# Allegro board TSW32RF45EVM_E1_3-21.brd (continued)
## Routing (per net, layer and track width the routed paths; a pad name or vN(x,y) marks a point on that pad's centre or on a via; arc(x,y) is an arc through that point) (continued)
P3.3VLMX:
  vias: v1(109.22,18.16) v1(109.22,17.14) v1(109.22,16.13) v1(110.11,18.16) v1(110.11,17.14) v1(110.11,16.13) v1(111,18.16) v1(111,17.14) v1(111,16.13)
V1: length 33.6
  TOP w0.229: v1(32.84,46) 32.99,45.85 U8.1 ; U7.1 v2(32.99,42.65)
  L4_SIG w0.127: JP3.1 41.38,65.15 40.97,65.15 40.56,64.74 40.56,61.11 40.31,60.86 39.29,60.86 38.79,60.35 v1(38.73,60.35) 38.66,60.35 38.23,59.92 37.06,59.92 31.33,54.19 31.17,54.19 30.9,53.92 30.9,53.76 29.72,52.58 29.72,50.58 29.63,50.49 29.63,50.1 29.72,50.01 29.72,49.94 29.97,49.69 29.97,48.79 32.77,46 v1(32.84,46) 33.1,45.75 33.1,44.2 33.53,43.76 33.53,42.92 33.25,42.65 v2(32.99,42.65)
V2: length 32.9
  TOP w0.203: v1(32.49,40.44) 32.64,40.59 U7.5
  TOP w0.229: U8.5 v2(32.64,42.95)
  L4_SIG w0.127: JP3.3 41.66,60.35 v1(39.88,60.35) 39.52,60.35 34.35,55.18 33.46,55.18 32.68,54.39 32.68,53.51 32,52.83 32,49.98 31.75,49.73 31.75,48.51 32.2,48.07 arc(32.22,48.03) 32.23,47.98 32.23,47.73 33.87,46.09 33.87,45.02 34.23,44.66 34.23,43.37 33.99,43.13 33.99,42.04 32.49,40.54 v1(32.49,40.44) 32.26,40.67 32.26,42.27 32.64,42.65 v2(32.64,42.95)
+VSA: length 2.6
  TOP w0.305: v1(23.37,39.24) 23.36,39.25 U2.11
  BOTTOM w0.508: v1(23.37,39.24) C34.1
+VSB: length 2.6
  TOP w0.305: U2.20 23.37,44.82 v1(23.37,46.23)
  BOTTOM w0.508: C25.1 v1(23.37,46.23)
A_IN_M: length 21.2
  TOP w0.483: C5.1 14.17,39.88 arc(13.4,39.56) 13.08,38.79 13.08,30.73 arc(11.43,26.76) 7.45,25.11 J2.1
A_IN_P: length 21.2
  TOP w0.483: C4.1 12.41,41.02 arc(11.42,40.61) 11.01,39.62 11.01,32.39 arc(10.65,31.52) 9.78,31.16 9.18,31.16 arc(8.35,31.5) 8,32.34 8,34.26 arc(7.71,34.97) 7,35.27 J1.1
ADC_CLK: length 1.7
  BOTTOM w0.483: J5.1 C28.1
ADC_CLKM: length 3.1
  TOP w0.229: U1.28 36.67,42.49 36.61,42.55 35.19,42.55 R26.1
  TOP w0.305: C430.2 34.94,42.29 R26.1
ADC_CLKP: length 3.1
  TOP w0.229: R26.2 35.09,42.93 36.61,42.93 36.67,42.99 U1.27
  TOP w0.305: R26.2 34.96,43.05 C429.2
ADC_SCLK: length 45.7
  TOP w0.127: v1(44.87,50.79) 44.87,50.3 44.77,50.2 44.77,50.01 44.77,50 44.77,48.97 44.74,48.94 44.74,48.65 44.04,47.96 44.04,47.69 U1.6
  L4_SIG w0.127: v1(54.38,24.36) 54.38,24.51 52.15,26.75 52.15,28.7 50.01,30.84 50.01,31.27 48.77,32.51 47.86,32.51 46.46,33.91 42.29,33.91 41.64,34.56 41.45,34.56 41.19,34.82 41.19,34.86 40.68,35.37 40.68,35.52 40.51,35.69 40.51,38.5 40.43,38.59 40.43,39.11 40.93,39.61 41.13,39.61 41.59,40.07 41.59,47.78 41.08,48.28 41.08,49.31 40.96,49.44 40.95,49.44 40.68,49.72 40.68,50.11 40.95,50.38 41.17,50.38 41.21,50.42 43.79,50.42 44.16,50.79 v1(44.87,50.79)
  BOTTOM w0.127: v1(54.38,24.36) 54.41,24.33 U13.2
ADC_SDIO: length 39.6
  TOP w0.127: U1.5 44.49,47.92 45,48.43 45,48.84 45.02,48.86 45.02,49.9 45.03,49.9 45.03,50.09 v1(45.95,51.02)
  L4_SIG w0.127: v1(57.81,25.35) 57.81,26.06 55.25,28.63 54.18,28.63 50.14,32.66 50.14,33.35 45.26,38.23 44.73,38.23 44.37,38.58 44.37,47.19 44.93,47.75 44.93,50 v1(45.95,51.02)
  BOTTOM w0.127: v1(57.81,25.35) 57.81,24.08 57.41,23.68 U13.3
ADC_SDO: length 43.5
  TOP w0.127: v1(41.53,48.46) 41.49,48.42 U1.11
  L4_SIG w0.127: v1(47.68,48.13) 47.42,48.13 47.4,48.15 46.77,48.15 45.64,47.02 45.64,38.48 48.13,35.99 48.64,35.99 54.18,30.45 54.64,30.45 58.32,26.77 58.32,25.12 56.72,23.52 v1(54.99,23.52)
  BOTTOM w0.127: v1(41.53,48.46) 41.53,48.39 42.3,47.61 46.09,47.61 46.62,48.15 47.4,48.15 47.42,48.13 v1(47.68,48.13) ; v1(54.99,23.52) 55.48,23.03 U13.4
ADC_SEN: length 39.4
  TOP w0.127: U1.7 43.49,47.86 44.32,48.68 v1(44.33,49.15)
  L4_SIG w0.127: v1(44.33,49.15) 44.07,48.89 44.07,48.21 42.98,47.12 42.98,38.58 43.38,38.18 44.24,38.18 44.68,37.74 45.14,37.74 46.95,35.93 46.95,34.84 50.51,31.29 50.51,30.88 51.19,30.2 52.14,30.2 53.07,29.27 53.07,28.53 52.65,28.12 52.65,26.72 54.79,24.59 54.79,24.58 54.83,24.54 54.83,24.17 54.57,23.91 53.61,23.91 v1(53.39,24.13)
  BOTTOM w0.127: v1(53.39,24.13) 55.14,22.38 U13.5
AINM: length 7.6
  TOP w0.229: C3.2 37.88,33.66 39.37,33.66 40.05,34.33 40.05,37.11 39.99,37.17 U1.41
  TOP w0.483: L13.2 37.53,34.01 C3.2
AINP: length 8.2
  TOP w0.229: C3.1 37.94,33.27 39.53,33.27 40.43,34.18 40.43,37.11 40.49,37.17 U1.42
  TOP w0.483: C3.1 37.53,32.86 L7.2
B_IN_M: length 21.2
  TOP w0.483: J4.1 7.45,60.36 arc(11.43,58.72) 13.08,54.74 13.08,46.68 arc(13.4,45.91) 14.17,45.59 C111.1
B_IN_P: length 21.2
  TOP w0.483: C110.1 12.41,44.45 arc(11.42,44.86) 11.01,45.85 11.01,53.09 arc(10.65,53.95) 9.78,54.31 9.18,54.31 arc(8.35,53.97) 8,53.13 8,51.21 arc(7.71,50.5) 7,50.2 J3.1
BINM: length 7.6
  TOP w0.229: C6.2 37.88,51.82 39.37,51.82 40.05,51.14 40.05,48.36 39.99,48.3 U1.14
  TOP w0.483: C6.2 37.53,51.46 L12.2
BINP: length 8.2
  TOP w0.229: U1.13 40.49,48.3 40.43,48.36 40.43,51.29 39.53,52.2 37.94,52.2 C6.1
  TOP w0.483: C6.1 37.53,52.61 L11.2
CE: length 18.4
  L6_PWR w0.305: v1(63.27,63.7) 63.22,63.65 54.18,63.65 53.09,64.74 49.07,64.74 JP2.2
  BOTTOM w0.305: U10.1 63.26,63.69 v1(63.27,63.7)
CLK-IN: length 4.2
  BOTTOM w0.483: R56.1 T6.6 77.19,62.81 R59.1 R57.2
CLK_LAO_0M: length 39.8
  BOTTOM w0.165: 138.05,52.01 138.11,52.07 142.07,52.07 142.24,51.9 J10.G7
  BOTTOM w0.203: R79.2 105.04,52.69 105.08,52.66
  BOTTOM w0.229: 138.05,52.01 132.96,52.01 131.09,50.14 129.13,50.14 127.3,51.97 105.77,51.97 105.08,52.66
CLK_LAO_0P: length 39.8
  BOTTOM w0.165: 138.05,52.39 138.11,52.32 142.07,52.32 142.24,52.49 J10.G6
  BOTTOM w0.203: R75.2 105.3,52.98 105.33,52.94
  BOTTOM w0.229: 138.05,52.39 132.8,52.39 130.93,50.52 129.29,50.52 127.46,52.35 107.72,52.35 107.37,52.7 106.89,52.7 106.54,52.35 105.92,52.35 105.33,52.94
CLKIN1_N: length 6.5
  BOTTOM w0.229: C74.2 87.4,64.64 87.41,64.66 87.46,64.66 87.5,64.69 88.19,64.69 C75.2 88.32,64.72 89.08,63.96 91.25,63.96 91.7,63.51 91.7,62.87 91.76,62.81 U3.35
CLKIN1_P: length 6.1
  BOTTOM w0.229: U3.34 91.26,62.81 91.32,62.87 91.32,63.35 91.1,63.58 88.92,63.58 88.22,64.27 87.57,64.27 87.38,64.08 C73.2
CLKINN: length 4.4
  BOTTOM w0.483: T6.3 84.4,65.35 R60.2 85.12,64.64 C74.1
CLKINP: length 5.4
  BOTTOM w0.483: R56.2 T6.1 84.05,62.81 R60.1 85.04,63.8 R55.1 86,63.88 C73.1
CLKLA_0M: length 6.3
  BOTTOM w0.203: R78.1 104.23,53.12 R79.1
  BOTTOM w0.229: U3.63 99.97,54.1 100.03,54.16 100.56,54.16 100.7,54.31 102,54.31 102.33,53.98 102.69,53.98 103.02,54.31 103.45,54.31 103.69,54.07 103.69,53.73 R78.1
CLKLA_0P: length 6.3
  BOTTOM w0.203: R77.1 104.86,53.78 R75.1
  BOTTOM w0.229: R77.1 104.26,54.31 103.99,54.31 103.61,54.69 100.54,54.69 100.4,54.54 100.03,54.54 99.97,54.6 U3.62
CLKM: length 53.5
  TOP w0.229: v1(48.31,58.93) 48.31,59.5 48.54,59.73 49.35,59.73 50.9,58.18 v1(50.9,56.41)
  BOTTOM w0.229: C9.2 90.27,48.02 90.46,47.83 90.46,46.98 90.04,46.56 89.11,46.56 88.91,46.76 88.91,46.97 88.71,47.17 88.43,47.17 88.23,46.97 88.23,46.76 88.03,46.56 59.69,46.56 58.92,47.33 58.92,47.61 59.06,47.74 59.06,48.03 58.86,48.23 58.57,48.23 58.44,48.09 58.15,48.09 52.57,53.68 52.57,54.24 52.37,54.44 51.81,54.44 51.54,54.71 51.54,55.87 50.99,56.41 v1(50.9,56.41)
CLKP: length 53.5
  TOP w0.229: v1(51.03,55.68) 51.37,56.02 51.37,56.61 51.28,56.7 51.28,58.34 49.51,60.11 48.54,60.11 48.31,60.34 v1(48.34,60.91)
  BOTTOM w0.229: C8.2 91.03,48.02 90.84,47.83 90.84,46.82 90.2,46.18 59.53,46.18 51.16,54.55 51.16,55.55 v1(51.03,55.68)
CMA: length 3
  TOP w0.127: U2.21 22.86,45.98 R2.2 v1(22.35,47.62)
CMB: length 3
  TOP w0.127: U2.10 22.86,39.49 R7.2 v1(22.35,37.85)
CP1: length 37.8
  L4_SIG w0.305: v1(87.86,61.11) 88.32,61.11 88.82,61.62 88.82,63.11 89.36,63.65 92.18,63.65 93.09,62.74 95.58,62.74 97.51,64.67 108.41,64.67 108.99,65.25 110.21,65.25 111.2,64.26 117.45,64.26 118.95,62.76 v1(119.2,62.76)
  BOTTOM w0.305: v1(87.86,61.11) 87.86,61.11 U3.32
CP2: length 5.6
  BOTTOM w0.305: U3.46 97.27,62.46 97.57,62.76 99.62,62.76 99.97,62.41 C72.1 101.96,62.41 C71.1
CPOUT: length 15
  TOP w0.229: v1(61.75,57.35) 65.33,60.93 v1(65.33,66.32)
  BOTTOM w0.229: U10.12 59.76,57.64 60.05,57.35 v1(61.75,57.35) ; v1(65.33,66.32) 65.28,66.37 C395.1 63.75,66.37 R182.1
DA0_M: length 2.8
  TOP w0.229: C14.1 49.64,41.81 48.22,41.81 48.1,41.94 47.19,41.94 U1.62
DA0_P: length 2.8
  TOP w0.229: C13.1 49.59,41.43 48.07,41.43 47.94,41.55 47.21,41.55 U1.61
DA0M: length 106.8
  TOP w0.229: C14.2 50.61,41.78 54.89,41.78 58.27,38.4 136.04,38.4 139.26,41.63 140.91,41.63 145.49,46.2 149.13,46.2 149.83,45.5 149.83,44.83 149.38,44.37 148.89,44.37 148.59,44.07 v1(148.59,43.94)
DA0P: length 106.8
  TOP w0.229: C13.2 50.61,41.4 54.73,41.4 58.11,38.02 136.19,38.02 139.42,41.25 141.07,41.25 141.75,41.93 142.21,41.93 142.52,42.24 142.52,42.7 144.39,44.57 144.67,44.57 144.9,44.34 145.18,44.34 145.38,44.55 145.38,44.83 145.16,45.05 145.16,45.34 145.64,45.82 148.97,45.82 149.45,45.34 149.45,44.98 149.22,44.75 148.89,44.75 148.59,45.06 v1(148.59,45.21)
DA1_M: length 3.1
  TOP w0.229: U1.59 47.4,40.49 47.46,40.43 48.4,40.43 49.19,39.64 49.63,39.64 C16.1
DA1_P: length 3.1
  TOP w0.229: U1.58 47.38,39.99 47.44,40.05 48.24,40.05 49.03,39.26 49.6,39.26 C15.1
DA1M: length 108.3
  TOP w0.229: v1(149.86,41.4) 150.34,41.88 150.75,41.88 151.21,42.33 151.21,43.34 150.75,43.79 149.35,43.79 148.79,43.23 146.3,43.23 142.59,39.52 140,39.52 136.77,36.3 57.05,36.3 53.73,39.62 50.61,39.62 C16.2
DA1P: length 108.2
  TOP w0.229: v1(149.86,42.67) 150.27,42.26 150.6,42.26 150.83,42.49 150.83,43.18 150.6,43.41 149.5,43.41 148.95,42.85 146.46,42.85 146.18,42.57 146.18,42.28 146.27,42.19 146.27,41.9 146.07,41.7 145.79,41.7 145.69,41.8 145.41,41.8 143.79,40.18 143.79,39.9 143.9,39.79 143.9,39.5 143.7,39.3 143.41,39.3 143.3,39.41 143.02,39.41 142.75,39.14 140.16,39.14 136.93,35.92 56.9,35.92 53.57,39.24 50.61,39.24 C15.2
DA2_M: length 3.3
  TOP w0.229: U1.56 47.4,38.99 47.46,38.93 48,38.93 49.42,37.51 49.66,37.51 C18.1
DA2_P: length 3.4
  TOP w0.229: U1.55 47.33,38.49 47.39,38.55 47.84,38.55 49.28,37.11 49.59,37.11 C17.1
DA2M: length 106.4
  TOP w0.229: C18.2 50.61,37.47 52.81,37.47 55.96,34.32 137.38,34.32 140.35,37.29 142.67,37.29 146.81,41.43 148.87,41.43 149.75,40.55 149.75,39.77 149.3,39.32 148.89,39.32 148.59,39.02 v1(148.59,38.86)
DA2P: length 106.4
  TOP w0.229: v1(148.59,40.13) 148.59,39.93 148.82,39.7 149.14,39.7 149.37,39.93 149.37,40.39 148.72,41.05 146.96,41.05 146.36,40.44 146.36,40.16 146.59,39.92 146.59,39.64 146.39,39.43 146.11,39.43 145.87,39.67 145.59,39.67 142.82,36.91 142.05,36.91 141.75,36.6 141.36,36.6 141.06,36.91 140.51,36.91 137.54,33.93 55.8,33.93 52.65,37.08 50.61,37.08 C17.2
DA3_M: length 5.3
  TOP w0.229: U1.54 46.44,37.79 46.44,37.56 47.29,36.7 48.17,36.7 48.39,36.47 48.39,36.15 48.26,36.02 48.26,35.74 48.69,35.31 49.62,35.31 C20.1
DA3_P: length 5.3
  TOP w0.229: U1.53 46.06,37.77 46.06,37.4 48.53,34.92 49.62,34.92 C19.1
DA3M: length 107.2
  TOP w0.229: C20.2 50.61,35.31 51.72,35.31 54.84,32.18 145.33,32.18 145.68,32.54 146.01,32.54 146.37,32.18 148.03,32.18 149.89,34.04 149.89,34.32 149.68,34.53 149.68,34.82 149.88,35.02 150.16,35.02 150.37,34.81 150.66,34.81 151,35.15 151,36.54 150.77,36.77 150.3,36.77 v1(149.86,36.32)
DA3P: length 107.3
  TOP w0.229: v1(149.86,37.59) 150.3,37.15 150.93,37.15 151.38,36.7 151.38,35 148.19,31.8 54.69,31.8 51.56,34.92 50.61,34.92 C19.2
DB0_M: length 2.8
  TOP w0.229: U1.65 47.45,43.49 47.51,43.54 49.63,43.54 C22.1
DB0_P: length 2.8
  TOP w0.229: U1.66 47.45,43.99 47.51,43.93 49.6,43.93 C21.1
DB0M: length 103.9
  TOP w0.229: C22.2 50.61,43.56 55.63,43.56 59.05,40.13 135.33,40.13 138.58,43.38 140.64,43.38 144.2,46.94 149.4,46.94 v1(149.86,46.48)
DB0P: length 103.9
  TOP w0.229: C21.2 50.61,43.94 55.78,43.94 59.21,40.51 135.17,40.51 138.42,43.76 140.48,43.76 144.04,47.32 149.43,47.32 v1(149.86,47.75)
DB1_M: length 3.1
  TOP w0.229: C24.1 49.62,45.72 49.02,45.72 48.35,45.05 47.51,45.05 47.45,44.99 U1.68
DB1_P: length 3.1
  TOP w0.229: C23.1 49.62,46.1 48.87,46.1 48.19,45.43 47.49,45.43 47.43,45.49 U1.69
DB1M: length 102.8
  TOP w0.229: C24.2 50.61,45.72 56.54,45.72 60.1,42.16 134.47,42.16 144.32,52.02 146.94,52.02 147.32,51.64 v1(147.32,51.56)
DB1P: length 102.7
  TOP w0.229: v1(147.32,52.83) 147.32,52.78 146.94,52.4 144.16,52.4 134.31,42.55 60.25,42.55 56.7,46.1 50.61,46.1 C23.2
DB2_M: length 3.3
  TOP w0.229: C27.1 49.64,47.85 49.21,47.85 47.91,46.55 47.44,46.55 47.37,46.49 U1.71
DB2_P: length 3.3
  TOP w0.229: U1.72 47.38,46.99 47.43,46.94 47.75,46.94 49.05,48.23 49.59,48.23 C26.1
DB2M: length 106.2
  TOP w0.229: v1(149.86,51.56) 149.86,51.74 149.56,52.04 148.69,52.04 148.08,52.65 148.08,53.14 147.5,53.72 143.41,53.72 133.99,44.3 61.34,44.3 57.76,47.88 50.61,47.88 C27.2
DB2P: length 106.2
  TOP w0.229: C26.2 50.61,48.26 57.92,48.26 61.5,44.68 133.83,44.68 143.26,54.1 147.66,54.1 148.46,53.29 148.46,52.81 148.85,52.43 149.63,52.43 149.86,52.65 v1(149.86,52.83)
DB3_M: length 5.3
  TOP w0.229: U1.1 46.43,47.69 46.43,47.96 47.14,48.67 48.09,48.67 48.36,48.94 48.36,49.28 48.26,49.38 48.26,49.78 48.51,50.04 49.62,50.04 C31.1
DB3_P: length 5.3
  TOP w0.229: C30.1 49.62,50.42 48.36,50.42 46.05,48.11 46.05,47.7 U1.2
DB3M: length 106
  TOP w0.229: v1(149.86,56.64) 149.86,56.82 149.58,57.1 146.56,57.1 146.28,56.82 143.61,56.82 132.97,46.18 62.51,46.18 58.62,50.06 50.63,50.06 C31.2
DB3P: length 105.9
  TOP w0.229: v1(149.86,57.91) 149.86,57.71 149.63,57.48 146.41,57.48 146.13,57.2 143.45,57.2 132.81,46.56 62.67,46.56 58.78,50.44 50.58,50.44 C30.2
DCLKOUT10N: length 4.2
  BOTTOM w0.229: U3.55 99.51,58.11 99.57,58.17 101.75,58.17 R151.1 102.34,58.14 102.69,58.14 C171.1
DCLKOUT10P: length 4.1
  BOTTOM w0.229: C170.1 102.69,58.5 102.34,58.5 R152.1 101.8,58.52 99.59,58.52 99.51,58.61 U3.54
ENA: length 7.5
  TOP w0.127: U2.22 22.36,45.36 v2(21.89,45.82)
  BOTTOM w0.127: JP4.1 21.89,51.49 v2(21.89,45.82)
ENB: length 7.5
  TOP w0.127: v2(21.87,39.65) 22.36,40.14 U2.9
  BOTTOM w0.127: JP5.1 21.87,34.01 v2(21.87,39.65)
FMC_CTRL1: length 173.2
  L4_SIG w0.127: v1(34.16,54.74) 34.16,53.85 33.1,52.78 33.1,49.15 33.19,49.06 33.19,49.01 37.03,45.16 37.3,45.16 37.92,44.55 38.5,44.55 38.79,44.26 38.79,40.89 38.5,40.6 38.09,40.6 36.28,38.79 36.28,35.35 36.69,34.94 36.69,33.49 38.34,31.84 39.71,31.84 40.45,31.1 40.45,30.75 40.45,30.49 40.89,30.05 40.89,27.86 43.4,25.36 43.4,20.08 44.07,19.41 44.07,17.4 46.53,14.94 63.35,14.94 65.11,16.69 68.55,16.69 69.24,16 80.16,16 80.63,16.47 83.71,16.47 84.02,16.16 85.62,16.16 86.26,15.52 93.68,15.52 99.05,10.15 99.86,10.15 99.99,10.02 111.94,10.02 111.95,10.01 112.62,10.01 113.51,10.9 136.63,10.9 137.29,11.56 137.29,25.93 138.07,26.72 146.76,26.72 147.32,27.28 v3(147.32,27.43)
  BOTTOM w0.127: R165.1 33.58,52.24 34.16,52.83 v1(34.16,54.74)
FMC_CTRL2: length 162.4
  L4_SIG w0.127: v1(147.32,26.16) 146.58,25.43 138.84,25.43 137.76,24.35 137.76,11.18 136.95,10.36 118.67,10.36 117.34,9.03 99.9,9.03 99.14,9.79 98.82,9.79 93.61,15 67.17,15 66.73,14.55 46.2,14.55 42.44,18.31 42.44,22.15 42.68,22.39 42.68,24.5 40.45,26.73 40.45,28.89 35.31,34.04 34.54,34.04 33.35,35.23 33.35,39.7 34.57,40.92 34.57,46.08 32.66,47.98 32.66,49.4 v1(32.36,49.71)
  BOTTOM w0.127: 32.76,50.83 32.76,50.11 v1(32.36,49.71)
FPGA_JESD_CLKM: length 55.2
  BOTTOM w0.165: 138.05,50.75 138.11,50.81 143.82,50.81 144.27,51.25 144.27,54.32 144.55,54.61 145.88,54.61 146.05,54.44 J10.D5
  BOTTOM w0.229: C69.2 98.09,48.25 98.09,47.57 99.49,46.18 133,46.18 137.57,50.75 138.05,50.75
FPGA_JESD_CLKP: length 55.2
  BOTTOM w0.165: J10.D4 146.05,55.03 145.88,54.86 144.45,54.86 144.01,54.43 144.01,51.35 143.72,51.06 138.14,51.06 138.07,51.13 138.05,51.13
  BOTTOM w0.229: C67.2 98.48,48.26 98.48,47.73 99.65,46.56 100.37,46.56 100.57,46.76 100.57,46.81 100.77,47.02 101.05,47.02 101.25,46.81 101.25,46.76 101.45,46.56 132.84,46.56 135.87,49.58 135.87,49.89 136.22,50.25 136.53,50.25 137.41,51.13 138.05,51.13
FPGA_JESD_SYSREFM: length 50.6
  BOTTOM w0.165: J10.G10 142.24,48.09 142.07,48.26 138.13,48.26 138.07,48.2 138.05,48.2
  BOTTOM w0.203: R49.2 95.82,47.46 95.82,46.47 97.99,44.3 133.96,44.3 137.86,48.2
  BOTTOM w0.229: 138.05,48.2 137.86,48.2
FPGA_JESD_SYSREFP: length 50.6
  BOTTOM w0.165: 138.05,48.58 138.07,48.58 138.13,48.52 141.73,48.52 J10.G9
  BOTTOM w0.203: 137.86,48.58 137.82,48.58 137.81,48.57 137.71,48.57 137.49,48.35 137.49,48.33 133.81,44.65 133.46,44.65 133.25,44.86 132.8,44.86 132.59,44.65 98.14,44.65 97.2,45.59 97.2,45.84 97.31,45.95 97.31,46.2 97.13,46.38 96.88,46.38 96.77,46.27 96.52,46.27 96.18,46.62 96.18,47.46 R48.2
  BOTTOM w0.229: 138.05,48.58 137.86,48.58
GPIO1: length 49.9
  TOP w0.127: v1(36.63,47.52) 37.16,46.99 U1.19
  L4_SIG w0.127: v1(36.63,47.52) 38.74,47.52 39.7,48.49 39.7,49.71 41.35,51.36 42.11,51.36 42.28,51.54 47.4,51.54 48.62,50.32 48.95,50.32 55.4,43.87 55.93,43.87 63.86,35.94 64.48,35.94 67.72,32.71 67.72,31.8 TP3.1
GPIO2: length 30.3
  TOP w0.127: U1.63 v1(48.37,42.49)
  L4_SIG w0.127: v1(48.37,42.49) 48.37,42.81 48.87,43.31 55.75,43.31 63.7,35.36 63.7,35.03 67.41,31.32 TP7.1
GTXCLKM: length 4.1
  BOTTOM w0.203: C69.1 97.9,49.11 ; 97.88,49.9 98.11,50.12 98.11,51.07 97.84,51.33 97.84,51.87 97.77,51.94 U3.2 ; 97.9,49.82 R52.1
  BOTTOM w0.229: 97.9,49.11 97.9,49.87 97.88,49.9
GTXCLKP: length 4.1
  BOTTOM w0.203: 98.69,49.9 98.46,50.12 98.46,51.22 98.2,51.48 98.2,51.87 98.27,51.94 U3.1 ; 98.66,49.82 R53.1 ; C67.1 98.66,49.11
  BOTTOM w0.229: 98.69,49.9 98.66,49.87 98.66,49.11
INA+: length 5.6
  TOP w0.229: C4.2 R1.1 17.4,40.64 18.29,40.64 18.67,41.02 18.67,41.42 19.18,41.93 19.6,41.93 19.66,41.99 U2.5
INA-: length 5.6
  TOP w0.229: U2.6 19.66,41.49 19.6,41.54 19.33,41.54 19.05,41.26 19.05,40.86 18.45,40.26 17.4,40.26 R194.1 C5.2
INB+: length 5.6
  TOP w0.229: C110.2 R6.1 17.4,44.83 18.29,44.83 18.67,44.45 18.67,44.05 19.18,43.55 19.6,43.55 19.66,43.49 U2.2
INB-: length 5.6
  TOP w0.229: U2.1 19.66,43.99 19.6,43.93 19.33,43.93 19.05,44.21 19.05,44.61 18.45,45.21 17.4,45.21 17.02,45.59 C111.2
JESD_SYSREFM: length 5.2
  BOTTOM w0.203: R49.1 95.62,48.32 ; 95.62,49.03 R50.1 ; U3.4 96.77,51.94 96.84,51.87 96.84,51.58 95.83,50.58 95.83,49.35 95.59,49.11
  BOTTOM w0.229: 95.59,49.11 95.62,49.08 95.62,48.32
JESD_SYSREFP: length 5.2
  BOTTOM w0.203: 96.38,49.03 R51.1 ; R48.1 96.38,48.32 ; 96.4,49.11 96.19,49.32 96.19,50.43 97.2,51.43 97.2,51.87 97.27,51.94 U3.3
  BOTTOM w0.229: 96.4,49.11 96.38,49.08 96.38,48.32
LMK LOCKED:
  vias: v1(70.38,55.65)
LMK_CLKIN: length 4.8
  BOTTOM w0.483: J7.1 70.77,62.79 R58.1 R57.1
LMK_CSB: length 78.9
  L4_SIG w0.127: v1(88.52,50.8) 89.03,50.29 89.03,47.32 88.75,47.04 88.75,40.03 89.83,38.95 89.83,26.1 90.12,25.81 90.12,24.05 86.08,20.02 61.57,20.02 61.05,19.49 59.12,19.49 58.74,19.88 49.91,19.88 49.5,19.47 v1(47.34,19.47)
  BOTTOM w0.127: v1(88.52,50.8) 88.2,51.12 88.2,53.78 88.53,54.1 U3.18 ; U5.6 v1(47.34,19.47)
LMK_SCLK: length 111.9
  TOP w0.127: v1(51.92,25.37) 51.92,24.92 51.31,24.31 49.43,24.31 47.84,22.72 v1(47.39,22.72)
  L4_SIG w0.127: v1(57.73,57.23) 57.73,56.67 58.14,56.26 59.69,56.26 61.13,54.83 61.13,54.43 61.39,54.17 61.89,54.17 62.5,53.56 63.54,53.56 63.82,53.28 64.19,53.28 64.33,53.42 66.83,53.42 69.44,50.8 v1(86.64,50.8) 86.64,50.27 86.09,49.72 86.09,27.52 84.25,25.68 69.32,25.68 64.85,21.21 60.96,21.21 60.5,21.67 53.85,21.67 51.92,23.6 v1(51.92,25.37)
  BOTTOM w0.127: U5.1 v1(47.39,22.72) ; v1(86.64,50.8) 86.72,50.88 87.27,50.88 87.83,51.44 87.83,53.77 88.67,54.6 U3.19 ; U10.16 57.76,57.26 v1(57.73,57.23) ; U13.13 51.38,24.33 51.92,24.87 v1(51.92,25.37)
LMK_SDIO: length 116.7
  L4_SIG w0.127: v1(49.45,23.68) 48.8,23.68 48.11,22.99 v1(48.11,20.12) 49.3,20.12 49.99,20.8 54.91,20.8 55.17,20.55 56.85,20.55 57.42,21.12 60.38,21.12 60.7,20.8 65.1,20.8 69.47,25.17 84.43,25.17 86.69,27.43 86.69,35.56 87.07,35.94 87.07,37.52 86.59,38 86.59,49.4 87.15,49.96 87.15,51.28 v1(87.07,51.36) 69.49,51.36 66.93,53.92 64.43,53.92 64.19,54.17 63.82,54.17 63.58,53.92 62.67,53.92 62.04,54.55 62.04,54.77 61.75,55.05 61.58,55.05 60.97,55.66 60.97,56.83 59.89,57.91 59.89,58.88 59.46,59.31 58.32,59.31 57.25,58.24 v1(57.25,57.63)
  BOTTOM w0.127: U5.5 v1(48.11,20.12) ; U3.20 88.55,55.1 87.53,54.08 87.53,51.82 v1(87.07,51.36) ; U13.12 v1(49.45,23.68) ; U10.17 v1(57.25,57.63)
LMK_SDO: length 82.9
  TOP w0.127: v2(96.27,52.78) 96.27,52.45 94.89,51.08 89.89,51.08 v1(89.55,50.74)
  L4_SIG w0.127: v1(47.98,16.87) 50.47,19.35 56.19,19.35 56.33,19.49 58.33,19.49 58.8,19.02 61.49,19.02 61.95,19.48 86.36,19.48 90.55,23.67 90.55,26.29 90.28,26.56 90.28,43.62 90.27,43.63 90.27,50.01 v1(89.55,50.74)
  BOTTOM w0.127: U5.10 v1(47.98,16.87)
LMX_CLKB: length 23.1
  BOTTOM w0.483: C412.2 57.99,54.38 R192.2 61.81,53.75 arc(62.74,53.93) 63.52,54.45 66.39,57.32 arc(67.47,58.04) 68.74,58.29 75.05,58.29 arc(75.42,58.37) 75.74,58.58 arc(76.01,58.97) 76.1,59.44 R191.2
LMX_CLKM: length 30.1
  TOP w0.229: U8.3 32.28,44.98 v1(31.62,44.98)
  BOTTOM w0.229: v1(31.62,44.98) 31.62,44.07 31.39,43.84 30.81,43.84 30.05,44.6 30.05,44.88 30.19,45.02 30.19,45.35 30.05,45.49 30.05,45.75 30.32,46.02 30.48,46.02 30.82,45.68 30.98,45.68 31.11,45.81 31.11,46.14 30.93,46.31 30.93,46.63 31.34,47.04 33.81,47.04 45.75,58.98 46.02,58.98 46.29,59.25 46.29,59.52 46.49,59.73 47.73,59.73 47.92,59.54 C410.2
LMX_CLKP: length 30.1
  TOP w0.229: v1(31.62,42.32) 32.28,42.32 U7.3
  BOTTOM w0.229: C431.1 47.92,60.3 47.73,60.11 46.34,60.11 33.65,47.42 31.19,47.42 29.67,45.9 29.67,44.44 30.65,43.46 31.39,43.46 31.62,43.23 v1(31.62,42.32)
LMX_CSB: length 71.1
  L4_SIG w0.127: v1(44.65,17.53) 44.48,17.7 44.48,19.63 45.13,20.29 45.13,24.01 44.68,24.46 44.68,25.98 42.34,28.32 42.34,32.21 41.72,32.83 41.72,33.18 41.46,33.44 41.11,33.44 40.11,34.44 40.11,39.22 40.31,39.42 40.31,45.52 39.7,46.13 37.11,46.13 33.8,49.43 33.8,50.36 34.7,51.26 37.24,51.26 39.5,53.52 39.95,53.52 41.01,54.57 42.38,54.57 42.67,54.28 45.64,54.28 46.04,54.67 46.9,54.67 47.09,54.48 51.26,54.48 51.78,55 51.78,55.3 52.04,55.56 52.64,55.56 53.21,56.13 53.21,56.58 52.5,57.3 52.5,57.99 53.92,59.41 v1(53.92,61.32)
  BOTTOM w0.127: v1(53.92,61.32) 53.92,61.09 54.32,60.69 U10.24 ; U5.9 v1(44.65,17.53)
LMX_OSCM: length 39.6
  TOP w0.229: v1(65.01,57.81) 65.29,58.09 79.55,58.09 87.55,66.09 89.46,66.09 v1(89.69,65.86)
  BOTTOM w0.203: U10.9 61.87,59.69 61.93,59.75 ; v1(89.69,65.86) 90,66.17 90.39,66.17 91,66.78 92.72,66.78 92.9,66.6 92.9,66.45 93.08,66.27 93.33,66.27 93.51,66.45 93.51,66.6 93.69,66.78 94.04,66.78 94.32,66.5 94.32,65.8 C418.2
  BOTTOM w0.229: 61.93,59.75 61.94,59.74 62.36,59.74 64.03,58.06 64.75,58.06 v1(65.01,57.81)
LMX_OSCP: length 39.6
  TOP w0.229: v1(89.69,66.78) 89.38,66.47 87.4,66.47 79.39,58.47 65.26,58.47 v1(65.01,58.73)
  BOTTOM w0.203: v1(89.69,66.78) 89.94,66.52 90.25,66.52 90.86,67.13 94.19,67.13 94.68,66.64 94.68,65.8 C419.2 ; 62.1,60.12 62.09,60.12 61.94,60.12 61.87,60.19 U10.8
  BOTTOM w0.229: 62.1,60.12 62.52,60.12 64.19,58.45 64.72,58.45 v1(65.01,58.73)
LMX_SDO: length 59.9
  L4_SIG w0.127: v1(52.68,56.36) 52.2,56.36 51.47,55.64 51.47,55.26 51.1,54.89 47.35,54.89 47.09,55.14 45.92,55.14 45.49,54.71 42.67,54.71 42.49,54.89 40.84,54.89 39.85,53.9 39.27,53.9 37.59,52.22 35.08,52.22 33.49,50.63 33.49,49.21 37.01,45.69 37.2,45.69 38.02,44.87 38.61,44.87 39.1,44.38 39.1,40.21 38.5,39.61 38.26,39.61 37.36,38.71 37.36,35.66 37.38,35.65 37.38,35.5 37,35.12 37,33.62 38.47,32.14 39.83,32.14 40.75,31.22 40.75,30.62 41.88,29.49 41.88,28.35 44.32,25.91 44.32,24.05 44.68,23.69 v1(44.68,22.07)
  BOTTOM w0.127: U5.2 v1(44.68,22.07)
OSCINN: length 7.3
  BOTTOM w0.229: U3.44 96.27,62.81 96.26,62.82 96.26,63.03 97.32,64.09 97.7,64.09 97.9,63.89 97.9,63.74 98.1,63.54 98.38,63.54 98.58,63.74 98.58,63.89 98.79,64.09 100.16,64.09 C86.2
  BOTTOM w0.305: C85.2 101.21,63.83 C86.2
OSCINP: length 7.4
  BOTTOM w0.229: C83.2 100.16,64.47 97.16,64.47 95.87,63.19 95.87,62.92 95.77,62.81 U3.43
  BOTTOM w0.305: C83.2 101.23,64.74 C82.2
OSCN: length 2.6
  BOTTOM w0.305: C85.1 101.96,63.83 R82.1 R76.2 104.31,63.83 C84.2
OSCOUTN: length 3.2
  BOTTOM w0.203: U3.41 94.77,62.77 94.69,62.84 94.69,64.26 94.84,64.41 ; C419.1 94.84,65.02 94.84,64.41 ; 94.84,64.41 R180.1
OSCOUTP: length 3.3
  BOTTOM w0.203: 94.16,64.41 R181.1 ; 94.16,64.41 94.16,65.02 C418.1 ; 94.16,64.41 94.34,64.23 94.34,62.84 94.27,62.77 U3.40
OSCP: length 2.6
  BOTTOM w0.305: C82.1 101.96,64.76 R74.1 R71.2 104.33,64.76 C81.2
OUTA+: length 2.6
  TOP w0.229: R4.1 26.22,40.76 26.22,40.93 25.61,41.54 25.55,41.49 U2.13
OUTA-: length 2.9
  TOP w0.229: 27.09,40.76 27.09,40.77 26.66,41.2 26.49,41.2 25.77,41.93 25.61,41.93 25.55,41.99 U2.14
OUTB+: length 2.6
  TOP w0.229: U2.18 25.55,43.99 25.61,43.93 26.22,44.54 26.22,44.71 R9.1
OUTB-: length 2.9
  TOP w0.229: R10.1 26.66,44.27 26.49,44.27 25.77,43.55 25.61,43.55 25.55,43.49 U2.17
PDN: length 79.3
  TOP w0.127: U1.50 44.49,37.51 44.58,37.43 44.58,37.13 44.75,36.96 44.75,36.75 44.76,36.75 44.76,28.29 v1(44.78,28.27)
  L4_SIG w0.127: JP1.2 96.52,22.35 93.14,18.97 93.14,18.39 69.93,18.39 69.44,18.87 62.08,18.87 61.62,18.42 50.22,18.42 48.16,16.36 47.75,16.36 47.19,16.92 47.19,18.97 46.15,20.02 46.15,24.54 45.47,25.22 45.47,26.59 44.78,27.28 v1(44.78,28.27)
PLL2 LOCKED:
  vias: v1(73.23,55.68)
RESET: length 85.9
  TOP w0.127: v1(43.77,27.56) 43.75,37.22 43.49,37.49 U1.48 ; SW1.2 90.03,4.25 93.45,7.66 v1(93.45,17.32)
  L4_SIG w0.127: v1(93.45,17.32) 70.87,17.32 70.45,17.73 52.38,17.73 50.34,15.7 47.57,15.7 44.87,18.4 44.87,19.24 45.62,19.99 45.62,24.26 45.09,24.79 45.09,26.24 v1(43.77,27.56)
  vias: v1(89.89,4.7)
RFOUTBM: length 6.3
  TOP w0.483: J6.1 v1(55.55,53.72)
  BOTTOM w0.305: v1(55.55,53.72) 54.94,54.33 C413.2
SCAN_EN: length 1.8
  TOP w0.229: v1(44.27,36.14) 44.27,37.08 44.15,37.21 44.15,37.43 v2(43.99,37.58) U1.49
STAT 0:
  vias: v1(76.07,55.7)
STAT 1:
  vias: v1(78.97,55.68)
SYNC: length 13.8
  TOP w0.229: TP16.1 83.92,52.55 90.58,52.55 91.59,51.54 94.53,51.54 v2(95.77,52.78)
SYNCBM: length 134.4
  TOP w0.229: U1.36 36.94,38.49 36,37.55 34.94,37.55 R168.1 R166.2 33.64,37.55 32.12,37.55 v1(31.89,37.32)
  BOTTOM w0.102: J10.G13 142.24,44.38 142.34,44.48 142.75,44.48 142.96,44.7 142.96,45.57 142.55,45.99 138.28,45.99 138.2,46.07 138.05,46.07
  BOTTOM w0.203: 138.05,46.07 137.9,46.07 134.38,42.55 93.24,42.55 81.05,30.35 34.54,30.35 30.43,34.47 30.43,35.58 30.61,35.76 30.81,35.76 30.99,35.94 30.99,36.19 30.81,36.37 30.68,36.37 30.43,36.63 30.43,37.13 30.91,37.62 31.59,37.62 v1(31.89,37.32)
SYNCBP: length 134.4
  TOP w0.229: U1.35 36.9,38.99 35.85,37.93 34.94,37.93 R169.1 R167.2 33.64,37.93 32.22,37.93 v1(31.89,38.27)
  BOTTOM w0.102: J10.G12 142.24,44.77 142.34,44.67 142.67,44.67 142.77,44.77 142.77,45.49 142.47,45.8 138.13,45.8 138.05,45.71
  BOTTOM w0.203: 138.05,45.71 134.52,42.19 93.39,42.19 81.2,30 34.4,30 30.07,34.32 30.07,37.28 30.76,37.97 31.59,37.97 v1(31.89,38.27)
SYSREF+: length 5.1
  BOTTOM w0.203: 93.33,49.03 R67.1 ; 93.36,49.11 93.16,49.31 93.16,50.62 92.19,51.58 92.19,51.87 92.26,51.94 U3.13 ; R65.1 93.33,48.32
  BOTTOM w0.229: 93.36,49.11 93.33,49.08 93.33,48.32
SYSREF-: length 5.2
  BOTTOM w0.203: 92.54,49.11 92.8,49.37 92.8,50.47 91.84,51.43 91.84,51.87 91.76,51.94 U3.14 ; R66.1 92.57,48.32 ; 92.57,49.03 R68.1
  BOTTOM w0.229: 92.57,48.32 92.57,49.08 92.54,49.11
SYSREFM: length 80.3
  TOP w0.229: v1(35.8,39.09) 35.96,39.25 36.46,39.25 36.73,39.52 37.03,39.52 37.07,39.49 U1.34
  BOTTOM w0.203: 92.53,46.81 92.61,46.74 92.61,46.69 ; 92.53,46.85 92.52,46.85 R69.1 92.61,46.69 ; 92.61,46.69 92.66,46.69 92.66,46.63 92.71,46.63 92.71,46.58 92.76,46.58 92.76,45.24 91.94,44.42 91.66,44.42 91.62,44.47 91.33,44.47 91.13,44.27 91.13,43.98 91.17,43.94 91.17,43.66 81.1,33.58 80.52,33.58 80.31,33.37 80.31,32.79 79.7,32.18 38.15,32.18 37.8,32.54 36.98,32.54 36.62,32.18 35.57,32.18 34.26,33.49 34.26,34.04 34.04,34.26 33.48,34.26 33.17,34.57 33.17,37.15 33.37,37.35 33.58,37.35 33.78,37.56 33.78,37.84 33.58,38.04 33.37,38.04 33.17,38.24 33.17,39.09 33.6,39.52 34.88,39.52 35.16,39.24 35.65,39.24 v1(35.8,39.09) ; R66.2 92.57,47.61
  BOTTOM w0.229: 92.53,46.81 92.53,46.85 92.57,46.85 92.57,47.61
SYSREFP: length 80.3
  TOP w0.229: v1(35.8,39.8) 35.98,39.63 36.3,39.63 36.58,39.9 37.01,39.9 37.09,39.99 U1.33
  BOTTOM w0.203: 93.14,46.58 93.19,46.58 R70.1 93.38,46.85 93.37,46.85 ; 93.14,46.58 93.37,46.81 ; 93.14,46.58 93.14,45.12 79.85,31.83 38,31.83 37.82,32 36.98,32 36.78,31.8 35.41,31.8 32.79,34.42 32.79,39.25 33.45,39.9 34.9,39.9 34.92,39.89 35.02,39.89 35.31,39.6 35.6,39.6 v1(35.8,39.8) ; R65.2 93.33,47.61
  BOTTOM w0.229: 93.33,47.61 93.33,46.85 93.37,46.85 93.37,46.81
TA+: length 9
  TOP w0.229: R4.2 27.52,39.46 27.69,39.46 28.07,39.09 28.07,33.91 28.73,33.25 29.26,33.25 29.65,32.86 30.1,32.86
TA-: length 8.6
  TOP w0.229: R5.2 27.96,39.9 27.96,39.73 28.45,39.24 28.45,34.07 28.89,33.63 29.26,33.63 29.65,34.01 30.1,34.01
TAA+: length 2.3
  TOP w0.483: L5.2 34.23,32.86 C2.1 34.35,32.86 L7.1
TAA-: length 2.3
  TOP w0.483: L13.1 34.35,34.01 C2.2 34.23,34.01 L6.2
TB+: length 9
  TOP w0.229: 30.1,52.61 29.65,52.61 29.26,52.23 28.73,52.23 28.07,51.56 28.07,46.39 27.69,46.01 27.52,46.01 R9.2
TB-: length 8.6
  TOP w0.229: 30.1,51.46 29.65,51.46 29.26,51.84 28.89,51.84 28.45,51.4 28.45,46.23 27.96,45.74 27.96,45.57 27.53,45.14
TBB+: length 2.3
  TOP w0.483: L11.1 34.35,52.61 C10.1 34.23,52.61 L8.2
TBB-: length 2.3
  TOP w0.483: L12.1 35.37,51.53 C10.2 34.23,51.46 L9.2
USBDM: length 37.9
  BOTTOM w0.229: U5.16 39.64,14.92 39.78,14.78 40.62,14.78 41.07,14.33 41.07,13.08 40.55,12.56 31.46,12.56 C103.1 30.82,12.56 28.39,12.56 23.7,7.87 10.88,7.87 10.72,7.71 J11.2
USBDP: length 37.9
  BOTTOM w0.203: C104.1 31.46,12.94
  BOTTOM w0.229: 31.46,12.94 40.4,12.94 40.69,13.23 40.69,14.17 40.46,14.4 39.75,14.4 39.62,14.27 U5.15 ; J11.3 10.72,8.51 10.97,8.26 13.59,8.26 13.94,8.61 14.67,8.61 15.02,8.26 15.45,8.26 15.71,8.51 16.14,8.51 16.39,8.26 16.83,8.26 17.08,8.51 17.51,8.51 17.77,8.26 18.2,8.26 18.45,8.51 18.88,8.51 19.14,8.26 19.57,8.26 19.76,8.44 arc(19.89,8.53) 20.04,8.56 20.52,8.56 20.83,8.26 23.55,8.26 28.23,12.94 30.82,12.94 C104.1
VCM: length 21.6
  TOP w0.127: C61.1 31.5,48.64 v1(30.99,49.15)
  TOP w0.254: 34.98,45.49 U1.22
  TOP w0.305: C61.1 32.89,47.57 34.98,45.49
  BOTTOM w0.127: v1(30.99,49.15) 30.99,49.91 30.61,50.29 30.61,52.45 28.96,54.1 28.83,54.1 TP2.1
Y2_N: length 13.9
  BOTTOM w0.229: Y1.4 111.18,56.92 110.95,57.15 110.95,57.6 110.55,58 109.81,58 108.99,58.82 108.99,63.52 108.4,64.11 107.65,64.11 R81.1
  BOTTOM w0.305: R80.1 106.6,63.83 R81.1
Y2_P: length 13.8
  BOTTOM w0.229: R73.1 107.65,64.49 108.56,64.49 109.37,63.68 109.37,58.98 109.97,58.38 110.53,58.38 110.95,58.8 110.95,59.23 111.18,59.46 Y1.5
  BOTTOM w0.305: R73.1 106.6,64.77 R72.1
YO2_N: length 0.9
  BOTTOM w0.305: C84.1 R80.2
YO2_P: length 0.9
  BOTTOM w0.305: C81.1 R72.2
N19631466: length 1.6
  TOP w0.305: v1(122.74,5.15) 122.74,5.98 C166.1
  BOTTOM w0.305: U12.14 v1(122.74,5.15)
N19631491: length 1.7
  TOP w0.305: R127.2 125.76,8.33 v1(126.59,8.33)
  BOTTOM w0.305: U12.8 v1(126.59,8.33)
N19631493: length 1.7
  TOP w0.305: R125.2 124.69,5.69 v1(124.69,5.16)
  BOTTOM w0.305: U12.11 v1(124.69,5.16)
N19631495: length 1.7
  TOP w0.305: R124.2 124.04,5.83 v1(124.04,5.15)
  BOTTOM w0.305: U12.12 v1(124.04,5.15)
N19631505: length 1.5
  TOP w0.305: R126.2 126.13,7.03 v1(126.68,7.03)
  BOTTOM w0.305: U12.10 v1(126.68,7.03)
N19879131: length 4.2
  BOTTOM w0.381: v1(5.26,9.09) 5.47,9.31 J11.4
N19879145: length 1.7
  BOTTOM w0.381: J11.1 11,6.91 v1(11.05,6.86)
  vias: v1(8.46,6.91) v1(9.35,6.91) v1(10.29,6.86) v1(33.27,14.58) v1(33.27,13.92) v1(33.96,14.25) v1(34.65,14.58) v1(34.65,13.92)
N19879167: length 16.9
  TOP w0.127: C101.1 42.71,17.53 42.63,17.45
  TOP w0.508: 42.63,17.45 v1(40.44,17.45)
  BOTTOM w0.381: 40.37,17.52 v1(40.44,17.45) ; R95.2 36.13,17.52
  BOTTOM w0.432: TP4.1 35.2,20.57 ; TP4.1 36.12,18.44 ; TP4.1 34.29,18.44 ; TP4.1 33.98,19.35 ; TP4.1 36.42,19.35 ; TP4.1 36.12,20.27 ; TP4.1 34.29,20.27 ; TP4.1 35.2,18.14
  BOTTOM w0.508: 40.37,17.52 U5.20 36.13,17.52
N19879302: length 10.4
  TOP w0.127: v1(48.71,16.22) 48.71,21.71 v1(49.38,22.38)
  BOTTOM w0.127: U5.11 v1(48.71,16.22) ; U13.10 v1(49.38,22.38)
N19879304: length 5.4
  TOP w0.127: v1(47.32,21.42) 48.85,22.94 v1(48.85,23.03)
  BOTTOM w0.127: U5.3 v1(47.32,21.42) ; U13.11 v1(48.85,23.03)
N19881704: length 14.5
  L4_SIG w0.127: v3(147.32,37.59) 146.02,37.59 140.87,32.44 139.78,32.44 136.58,29.24 v1(136.32,29.24)
N19881714: length 0.4
  TOP w0.127: v3(140.97,57.91) 140.94,57.91 R89.1
N19881723: length 1.5
  TOP w0.127: R88.1 133.25,29.24 D5.1
N19884870:
  vias: v1(111.56,62.74) v1(111.56,61.87) v1(112.12,62.31) v1(112.67,62.74) v1(112.7,61.87) v1(113.61,62.79) v1(114.58,62.71) v1(115.7,62.69) v1(116.84,62.71)
N19884947:
  vias: v1(119.28,58.67)
N19886018: length 4.1
  BOTTOM w0.203: R64.1 90.5,50.16 90.5,50.88 90.84,51.21 90.84,51.87 90.76,51.94 U3.16
  BOTTOM w0.229: C9.1 90.27,49.8 R64.1
N19886020: length 4.1
  BOTTOM w0.203: U3.15 91.26,51.94 91.19,51.87 91.19,51.06 90.86,50.73 90.86,50.13 R63.1
  BOTTOM w0.229: C8.1 91.03,49.78 R63.1
N19887754: length 2.3
  TOP w0.381: v1(95.28,63.53) 94.82,63.53 FB8.2
  BOTTOM w0.305: U3.42 95.27,63.52 v1(95.28,63.53)
N19887756:
  vias: v2(97.76,62.28) v2(97.77,61.93) v2(97.76,61.57)
N19887760:
  vias: v2(98.76,59.11) v2(99.1,59.11) v2(99.44,59.13)
N19887762:
  vias: v2(98.73,53.59) v2(99.1,53.6) v2(99.47,53.59)
N19887789: length 22.7
  L4_SIG w0.127: v1(70.38,54.08) 72.59,54.08 72.78,54.27 72.78,54.29 73.04,54.55 73.06,54.55 76.15,57.64 76.15,57.89 76.61,58.34 80.01,58.34 81.86,60.2 82.63,60.2 82.8,60.02 83.29,60.02 83.88,60.62 88.84,60.62 v1(88.98,60.48)
  BOTTOM w0.127: U3.31 89.11,60.61 v1(88.98,60.48)
N19887795: length 33.6
  L4_SIG w0.127: v1(73.23,54.1) 75.4,56.27 84.44,56.27 85.57,57.4 90.4,57.4 90.82,57.82 98.92,57.82 99.78,58.69 99.78,61.79 v1(99.64,61.93)
  BOTTOM w0.127: v1(99.64,61.93) 99.24,62.33 98.4,62.33 98.27,62.2 U3.48
N19887804: length 24.8
  L4_SIG w0.127: v1(78.97,54.1) 79.45,54.58 85.09,54.58 86.83,56.32 90.36,56.32 90.82,55.87 100.61,55.87 v1(100.84,56.1)
  BOTTOM w0.127: U3.59 v1(100.84,56.1)
N19887822: length 26.4
  L4_SIG w0.127: v1(100.17,56.6) 99.9,56.87 86.87,56.87 85.04,55.04 76.99,55.04 v1(76.07,54.13)
  BOTTOM w0.127: U3.58 v1(100.17,56.6)
N19887828: length 1.9
  TOP w0.381: C96.1 91.85,52.83 92.53,52.15 v1(92.76,52.15)
  BOTTOM w0.305: U3.12 v1(92.76,52.15)
N19887830: length 1
  TOP w0.254: 93.21,53.07 93.27,53.01 v2(93.27,52.43) ; 93.21,53.07 v2(93.27,53.14) ; 93.21,53.07 C97.1
  vias: v2(93.27,52.78)
N19887836: length 3.3
  TOP w0.254: 94.01,52.91 v2(93.78,53.14) 93.78,52.79 ; 93.78,52.45 93.78,52.76 v2(93.77,52.78)
  TOP w0.305: C88.2 v2(93.75,52.43) 94.23,52.73 C88.2 ; C88.2 93.9,52.91 v2(93.77,52.78)
  BOTTOM w0.305: v2(93.77,52.78) v2(93.75,52.43)
  vias: v2(90.75,62.28) v2(90.76,61.93) v2(90.75,61.57) v2(92.25,62.28) v2(92.26,61.93) v2(92.25,61.57)
N19887876: length 1.9
  BOTTOM w0.305: v1(93.4,63.68) 93.77,63.31 U3.39
N19887878: length 1.8
  TOP w0.305: FB9.2 96.77,63.62 v1(96.77,62.78)
  BOTTOM w0.305: U3.45 v1(96.77,62.78)
N19887910: length 1.3
  BOTTOM w0.305: v1(88.95,55.6) v2(89.61,55.6) v2(90.22,55.6)
N19887912: length 1.5
  BOTTOM w0.305: v1(88.65,53.59) 88.67,53.62 v2(89.64,53.62) 89.66,53.59 v2(90.09,53.59)
N19887930: length 1.6
  BOTTOM w0.305: U3.26 88.99,58.11 v1(88.95,58.06) ; v2(90.14,58.12) v2(89.59,58.12)
N19893167: length 17.1
  TOP w0.483: C372.1 v1(29.03,43.94)
  BOTTOM w0.483: v1(29.03,43.94) 23.71,43.94 23.64,44.02 21.58,44.02 21.55,43.99 17.4,43.99 17.34,43.94 T5.3
N19893194: length 17.1
  TOP w0.483: C373.1 v1(29.03,41.4)
  BOTTOM w0.483: T5.1 21.5,41.4 21.58,41.33 23.64,41.33 23.71,41.4 v1(29.03,41.4)
N19893222: length 2
  BOTTOM w0.483: C28.2 T5.4
N19893438: length 2.3
  BOTTOM w0.127: T5.2 v1(11.14,42.67)
N19895463: length 1.3
  TOP w0.229: U8.4 32.26,43.94 C372.2
N19895477: length 1.3
  TOP w0.229: C373.2 32.2,41.4 U7.4
N19955835: length 0.8
  BOTTOM w0.508: v1(46.53,5.44) 46.53,5.66 U15.4
N20015888: length 34.6
  BOTTOM w0.229: J13.1 130.15,57.99 129.84,57.68 127.35,57.68 124.18,54.51 109.14,54.51 105.17,58.49 103.72,58.49 C170.2
N20015984: length 34.8
  BOTTOM w0.229: J9.1 130.15,56.97 129.82,57.3 127.51,57.3 124.33,54.13 108.99,54.13 105.01,58.11 103.67,58.11 C171.2
N20042801: length 1.7
  BOTTOM w0.305: R139.2 71.05,17.86 U16.7
N20043120: length 1.9
  BOTTOM w0.305: R138.2 70.71,18.51 U16.6
N20043460: length 1.7
  BOTTOM w0.305: U16.9 71.07,16.56 R140.2
N20043630: length 1.9
  BOTTOM w0.305: R141.2 70.71,15.91 U16.10
N20048856: length 1.7
  BOTTOM w0.305: R137.2 67.7,21.33 U16.4
N20080651: length 11.6
  TOP w0.508: SJP5.2 54.94,26.21 56.17,24.98 v1(56.44,24.98)
  BOTTOM w0.305: v1(56.44,24.98) 53.35,24.98 52.2,23.83 52.2,21.49 51.79,21.08 U13.8
N20101312: length 2.6
  TOP w0.305: U14.3 59.22,3.7 R132.2 R134.1
N20101314: length 16.6
  TOP w0.381: L1.1 58.97,12.38 58.97,9.75 ; 58.97,9.75 59.31,10.31 59.31,11.51 58.91,12.36 ; 58.97,9.75 59.05,10.69 58.91,12.36 ; 58.97,9.75 58.74,10.25 58.74,12.18 58.91,12.36 ; 58.97,9.75 58.55,10.41 58.55,11.48 58.91,12.36 ; 58.97,9.75 U14.6
N20101373: length 2.9
  L6_PWR w0.305: v1(61.28,4.7) 60.88,5.11 59.49,5.11 59.11,4.72 v2(58.72,4.72)
  vias: v2(58.72,5.46) v2(58.72,5.08)
N20111831: length 2.6
  TOP w0.305: R155.1 R154.2 U11.3
N20111833: length 13.4
  TOP w0.381: L2.1 74.03,12.64 74.03,10.36 ; L2.1 74.3,10.39 ; L2.1 74.47,11.64 74.47,10.8 74.3,10.39 ; L2.1 73.76,11.75 73.76,11.04 74.03,10.36 ; 74.3,10.39 74.03,9.78 ; 74.03,10.36 74.03,9.78 ; 74.03,9.78 U11.6
N20111884: length 4.3
  TOP w0.305: U11.2 v1(73.78,4.8)
  L6_PWR w0.305: v1(73.78,4.8) 74.62,5.64 75.84,5.64 v1(76.63,4.85)
N20113515: length 4.2
  BOTTOM w0.381: C193.2 92.15,14.25 R143.2 ; R145.1 R143.2 ; R143.2 90.35,14.25 90.19,14.41 U17.16
N20114896: length 2.9
  TOP w0.305: v1(98.83,5.92) 98.69,6.06 U18.4
  TOP w0.508: v1(100.36,5.41) v1(99.21,5.41) 98.83,5.79 v1(98.83,5.92)
  vias: v1(100.1,15.57) v1(100.1,14.81) v1(100.06,14.05) v1(100.1,13.28) v1(100.1,12.52) v1(100.82,14.05) v1(100.86,15.57) v1(100.86,14.81) v1(100.86,13.28) v1(100.86,12.52) v1(101.71,14.05) v1(101.75,15.57) v1(101.75,14.81) v1(101.75,13.28) v1(101.75,12.52)
N20114915: length 2.7
  TOP w0.305: U18.3 98.19,5.42 R146.2 R147.1
N20114917: length 20.8
  TOP w0.305: 98.27,12.07 98.3,12.78 L3.1 ; 98.27,12.07 98.02,11.32 ; 98.27,12.07 L3.1 ; 98.02,11.32 L3.1 ; 98.02,11.32 97.94,11.07 ; 97.94,11.07 97.94,13.97 L3.1 ; 97.94,11.07 97.74,11.6 ; 97.94,11.07 U18.6 ; L3.1 97.43,12.85 97.41,12.6 97.54,12.12 ; L3.1 97.54,12.12 ; L3.1 97.74,11.6 ; 97.54,12.12 97.74,11.6
N20114968: length 4.3
  TOP w0.305: v1(97.43,5.94) 97.69,6.2 U18.2
  L6_PWR w0.305: v1(97.43,5.94) 98.04,6.55 100.23,6.55 v1(100.36,6.43)
N20150497:
  vias: v1(66.4,15.04)
N20151052:
  vias: v1(85.24,15.71)
N20152729: length 2.1
  TOP w0.305: SJP4.2 96.42,5.79 97.19,6.56 U18.1
N20210385: length 61.6
  TOP w0.229: v1(34.75,50.12) 35.79,49.08 35.79,47.12 36.42,46.49 U1.20
  L4_SIG w0.127: TP8.1 76.91,27.69 73.53,27.69 71.92,29.3 71.92,29.5 71.66,29.76 71.41,29.76 63.47,37.69 63.47,38.4 55.45,46.43 54.71,46.43 49.24,51.89 42.49,51.89 41.68,52.7 40.67,52.7 39.85,51.89 39.07,51.89 36.96,49.78 35.46,49.78 35.13,50.12 v1(34.75,50.12)
  BOTTOM w0.229: v1(34.75,50.12) 34.29,50.57 R165.2
N20210389: length 68.6
  TOP w0.229: U1.21 36.67,45.99 36.61,46.05 36.17,46.05 35.26,46.96 35.26,48.69 34.33,49.61 v1(34.25,49.61)
  L4_SIG w0.127: v1(34.25,49.61) 34.25,50.24 34.93,50.93 37.59,50.93 39.29,52.63 39.65,52.63 40.69,53.67 41.4,53.67 42.44,52.63 49.21,52.63 53.4,48.44 54.2,48.44 55.44,47.2 55.44,47.19 61.72,40.91 61.86,40.91 69.51,33.25 69.51,32.4 71.24,30.67 71.26,30.67 73.81,28.12 81.56,28.12 TP9.1
  BOTTOM w0.229: v1(34.25,49.61) 33.75,50.11 R164.2
N20213760:
  vias: v1(84.48,4.83)
N20220969: length 1.4
  TOP w0.305: C387.1 110.07,7.18 v1(110.07,6.44)
  BOTTOM w0.305: U9.14 v1(110.07,6.44)
N20220990: length 1.5
  TOP w0.305: R171.2 113.08,9.53 v1(113.84,9.53)
  BOTTOM w0.305: U9.8 v1(113.84,9.53)
N20220992: length 1.4
  TOP w0.305: v1(112.32,6.5) R172.2
  BOTTOM w0.305: v1(112.32,6.5) 112.02,6.8 U9.11
N20220994: length 1.7
  TOP w0.305: v1(111.37,6.36) 111.37,7.02 R170.2
  BOTTOM w0.305: U9.12 v1(111.37,6.36)
N20221006: length 1.2
  TOP w0.305: v1(113.39,7.72) R173.2
  BOTTOM w0.305: U9.10 113.29,8.23 113.39,8.13 v1(113.39,7.72)
N20227487: length 2.6
  BOTTOM w0.305: U10.27 53.99,62.19 53.91,62.28 53.37,62.28 C400.2 52.73,62.2 v1(52.73,62.18)
N20231187: length 2.4
  BOTTOM w0.305: C403.2 63.19,62.69 U10.3
N20232417: length 1
  BOTTOM w0.305: v1(59.28,65.51) 59.26,65.49 U10.38
N20232915: length 1.4
  BOTTOM w0.305: U10.29 53.72,63.19 v1(53.64,63.27)
N20233092: length 2.9
  TOP w0.305: v2(58.17,65.99) C406.2 58.17,65.79 v1(58.34,65.61)
  BOTTOM w0.305: 58.26,65.89 58.34,65.81 v1(58.34,65.61) ; 58.26,65.89 58.26,65.6 ; 58.26,65.89 v2(58.17,65.99) 58.17,65.79 v1(58.34,65.61) ; 58.26,65.6 58.27,65.61 v1(58.34,65.61) ; 58.26,65.6 U10.36
N20234062: length 0.9
  TOP w0.305: v2(56.77,64.11) 56.77,64.34 C407.2 56.57,64.64 v2(56.77,64.85)
  vias: v2(56.76,64.47)
N20235277: length 7.2
  BOTTOM w0.229: U10.23 54.31,60.19 R175.1 51.65,60.08 49.17,60.08 C409.1
N20235286: length 7.2
  BOTTOM w0.229: U10.22 54.31,59.69 R176.1 51.76,59.7 49.08,59.7 C410.1
N20237052: length 3.9
  BOTTOM w0.229: U10.18 56.76,58.41 56.76,57.43 57.82,56.36 R177.1 C412.1
N20237066: length 3.9
  BOTTOM w0.229: U10.19 56.26,57.51 R178.1 C413.1
N20239082: length 2.2
  BOTTOM w0.127: R179.2 53.72,64.21 54.24,63.69 U10.30
N20249678: length 1.1
  TOP w0.305: 60.86,59.18 v2(60.68,59.18) ; 60.86,59.18 60.81,59.23 61.01,59.23 v2(61.06,59.18) ; 60.86,59.18 v2(61.06,59.18) ; v2(61.06,59.18) v2(61.39,59.18)
N20251064: length 0.8
  BOTTOM w0.229: C394.2 R174.1
N20251377: length 1.7
  BOTTOM w0.229: C420.1 R183.1 R182.2
N20251505: length 5.8
  BOTTOM w0.229: R183.2 60.81,66.32 C421.1 60.68,66.45 57.94,66.45 57.71,66.22 57.71,65.33 57.76,65.27 U10.35
N20257347: length 15.5
  L4_SIG w0.127: v1(55.17,66.5) 56.29,65.38 56.29,63.75 55.88,63.35 55.88,57.43 54.79,56.33 53.72,56.33 v1(53.7,56.36)
  BOTTOM w0.127: v1(53.7,56.36) 54.05,56.36 55.76,58.08 U10.20
N20258125:
  vias: v1(54.46,66.5)
N20306930: length 1.4
  TOP w0.229: U8.6 33.27,43.98 33.5,43.75 33.5,43.28 C429.1
N20306944: length 1.5
  TOP w0.229: C430.1 33.53,42.09 33.53,41.54 33.3,41.31 U7.6
N20361040: length 1.9
  TOP w0.305: v1(131.28,4.87) 131.28,5.85 C36.1
  BOTTOM w0.305: U4.14 v1(131.28,4.87)
N20361065: length 2
  TOP w0.305: R11.2 v1(132.59,4.83)
  BOTTOM w0.305: U4.12 132.58,4.87 v1(132.59,4.83)
N20361077: length 2.2
  TOP w0.305: R12.2 134.67,6.9 v1(135.59,6.9)
  BOTTOM w0.305: U4.10 v1(135.59,6.9)
N20361858: length 2.3
  TOP w0.305: 134.24,9.4 135.25,9.4 v1(135.38,9.53)
  BOTTOM w0.305: U4.6 134.35,9.53 v1(135.38,9.53)
N20361961: length 3.1
  TOP w0.305: R13.2 134.94,7.55 v1(135.7,7.55)
  BOTTOM w0.305: U4.9 v1(135.7,7.55)
N20445187: length 1.2
  TOP w0.127: C437.2 16.89,43.31 R6.2
N20459699: length 1
  TOP w0.483: C433.2 L8.1
N20459721: length 1
  TOP w0.483: L9.1 C434.2
N20459741: length 1
  TOP w0.483: L5.1 C435.2
N20459761: length 1
  TOP w0.483: L6.1 C436.2
N20460250: length 1.2
  TOP w0.127: C438.2 16.89,46.74 R193.2
N20460913: length 1.2
  TOP w0.127: R194.2 16.89,38.73 C439.2
N20461153: length 1.2
  TOP w0.127: R1.2 16.89,42.16 C440.2
N183394940: length 2.7
  BOTTOM w0.305: R133.2 53.47,5.82 v1(54.71,4.57)
N198851401: length 0.9
  BOTTOM w0.305: C71.2 R54.1
N198852420: length 1
  BOTTOM w0.305: R47.1 86.84,60.22 C70.2

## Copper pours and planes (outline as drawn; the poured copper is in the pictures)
1.4V on TOP: 76.38,8.66 76.38,10.67 75.97,11.07 75.97,14.5 78.16,14.5 78.92,13.74 78.92,9.17 78.41,8.66
1.4V on BOTTOM: 76,9.98 76,14.83 82.19,14.83 82.19,16.33 84.51,16.33 84.51,11.07 85.39,11.07 85.39,9.86 84.18,8.64 77.34,8.64
5.0V_IN on TOP (solid shape): 46.91,6.85 42.39,6.85 42.39,10.66 46.91,10.66
5.0V_IN on TOP: 31.8,6.43 31.8,9.35 33.73,11.28 46.89,11.28 47.68,10.49 47.68,7.06 47.04,6.43 38.79,6.43 37.52,5.16 33.07,5.16
5.0V_IN on BOTTOM: 31.8,6.43 31.8,9.37 33.71,11.28 46.89,11.28 47.68,10.49 47.68,7.06 47.27,6.65 39.01,6.65 37.52,5.16 33.07,5.16
5VIN on TOP: 58.42,9.78 58.42,4.65 56.79,4.65 56.79,9.78
5VIN on TOP: 73.58,10.19 73.58,5.05 71.96,5.05 71.96,10.19
5VIN on TOP: 97.43,11.63 97.43,7.82 95.53,7.82 95.15,8.2 95.15,11.25 95.53,11.63
5VIN on TOP: 50.22,5.13 50.22,3.25 53.39,3.25 53.39,5.13
5VIN on TOP, BOTTOM: 42.21,5.79 42.21,2.87 45.64,2.87 45.64,5.79
5VIN on BOTTOM: 58.17,9.4 58.17,4.7 56.77,4.7 56.77,9.4
5VIN on BOTTOM: 118.14,5.61 118.14,6.35 118.64,6.35 119.51,7.21 121.46,7.21 121.46,6.35 123.6,6.35 123.6,4.34 123.11,3.86 119.89,3.86
5VIN on BOTTOM: 50.47,3.51 50.47,5.16 52.88,5.16 52.88,3.51
5VIN on BOTTOM: 127.6,6.64 128.04,7.09 130,7.09 130,6.22 132.13,6.22 132.13,4.57 132.21,4.5 132.21,3.28 128.88,3.28 127.6,4.56
5VIN on BOTTOM: 35.2,16.31 35.2,15.04 37.06,15.04 37.06,16.31
5VIN on BOTTOM: 105.46,6.93 105.46,8.53 108.79,8.53 108.79,7.67 110.92,7.67 110.92,5.66 110.44,5.18 107.21,5.18
5VIN on BOTTOM: 97.18,11.25 97.18,8.08 95.15,8.08 95.15,11.25
5VIN on BOTTOM: 73.25,9.8 73.25,5.11 71.93,5.11 71.93,9.8
5VIN on L3_PWR: 29.84,1.91 29.84,16.26 96.14,16.26 100.97,11.43 131.06,11.43 131.19,11.3 131.19,1.91
+2.2V on TOP: 63.12,4.83 63.12,8.26 60.83,8.26 60.83,15.32 65.79,15.32 65.79,13.08 66.42,12.45 66.42,4.83
+2.2V on BOTTOM: 60.71,14.71 60.71,10.8 63.12,8.38 66.55,8.38 66.55,10.92 65.91,11.56 65.91,15.37 65.28,15.37 65.28,16.69 62.69,16.69
+3.3V_LMX on TOP: 116.71,19.43 116.71,27.05 112.14,27.05 112.01,26.92 112.01,22.35 114.94,19.43
+3.3V_LMX on TOP: 57.63,63.6 57.63,65.23 59.49,65.23 59.49,63.6
+3.3V_LMX on L3_PWR: 112.06,21.59 112.06,31.12 84.45,31.12 57.15,58.42 55.12,58.42 54.23,59.31 54.23,66.04 65.41,66.04 90.17,41.28 120.65,41.28 120.65,21.59
+3.3V_LMXRF on TOP: 108.84,19.56 108.84,25.65 111.25,25.65 111.25,19.56
+3.3V_LMXRF on BOTTOM: 38.35,61.11 38.35,62.51 40.26,62.51 40.26,61.11
+3.3V_LMXRF on L3_PWR: 111.23,19.05 111.23,29.84 83.82,29.84 56.52,57.15 55.25,57.15 53.59,58.8 53.59,66.04 38.1,66.04 38.1,59.05 78.11,19.05
+3.3VCLK on TOP: 92.56,64.52 90.88,64.52 90.88,66.14 91.69,66.95 92.56,66.95
+3.3VCLK on TOP: 122.86,23.32 122.86,16.79 127.36,16.79 127.36,23.32
+3.3VCLK on TOP: 100.23,59.75 100.23,61.19 100.46,61.42 101.52,61.42 101.52,59.75
+3.3VCLK on TOP: 101.52,53.21 101.52,51.56 102.67,51.56 102.67,53.21
+3.3VCLK on TOP: 87.76,58.93 87.76,55.12 87.5,54.86 87.5,53.24 87.45,53.19 86.16,53.19 86.16,54.36 86.51,54.71 86.51,58.93
+3.3VCLK on BOTTOM: 122.68,18.03 122.68,22.99 127.64,22.99 127.76,22.86 127.76,18.67 127.06,17.97 122.75,17.97
+3.3VCLK on L6_PWR: 121.92,19.96 121.92,20.45 119.89,22.48 119.89,30.35 121.92,32.39 121.92,46.1 117.86,50.16 77.27,50.16 77.27,66.68 124.46,66.68 135.89,55.25 135.89,25.91 127.89,25.91 127.76,25.78 127.76,18.67 127.71,18.62 123.27,18.62
+4.5V on BOTTOM: 131.32,17.78 131.32,21.97 130.94,22.35 130.94,24.77 131.44,25.27 135.13,25.27 135.13,17.78
+4.5V on L6_PWR: 17.78,5.72 17.78,50.55 24.77,50.55 24.77,34.92 35.56,24.13 35.56,17.14 40.01,12.7 128.27,12.7 128.27,25.4 135.84,25.4 135.86,25.37 135.86,5.74 135.84,5.72
AVDD1.9V on TOP: 62.08,24.71 62.08,21.49 67.49,21.49 67.49,24.94 64.39,24.94 64.16,24.71
AVDD1.9V on BOTTOM: 61.85,19.69 61.85,20.83 62.13,21.11 62.13,24.66 63.65,24.66 64.01,25.02 66.68,25.02 67.06,24.64 67.06,21.08 66.55,20.57 66.55,19.05 65.15,19.05 65.15,17.65 63.88,17.65
AVDD1.9V on L3_PWR: 24.13,26.04 24.13,41.28 29.97,47.12 35.56,47.12 35.56,51.44 43.18,51.44 43.18,33.66 35.56,33.66 35.56,35.56 34.29,35.56 33.66,34.92 33.66,30.48 38.73,25.4 67.54,25.4 67.54,17.14 33.02,17.14
AVDD1.15V on BOTTOM: 89.46,21.24 82.78,21.24 82.78,24.92 85.82,24.92 85.82,24.03 86.29,23.57 92.63,23.57 92.63,21.23 89.46,21.23
AVDD1.15V on L6_PWR: 26.67,43.81 29.84,46.99 35.56,46.99 35.56,51.44 42.93,51.44 42.93,39.12 42.67,38.86 42.67,33.66 42.55,33.66 42.55,27.94 45.47,25.02 87.76,25.02 87.76,20.45 86.61,19.3 86.61,17.14 41.91,17.14 36.83,22.23 36.83,25.4 26.67,35.56
DVDD1.15V on TOP: 103.17,18.26 103.17,21.01 100.48,23.7 98.58,23.7 97.31,22.43 97.31,19.28 98.32,18.26
DVDD1.15V on TOP: 54.15,27.58 54.15,26.29 52.86,26.29 52.86,27.86 53.87,27.86
DVDD1.15V on BOTTOM: 97.79,17.93 97.79,23.27 101.04,23.27 101.04,17.93
DVDD1.15V on L6_PWR: 81.15,34.92 59.05,34.92 59.05,26.42 47.24,26.42 43.56,30.1 43.56,35.43 43.05,35.94 43.05,37.85 43.56,38.35 43.56,47.47 43.31,47.75 43.31,51.44 59.05,51.44 59.05,46.36 87.02,46.36 103.5,29.87 103.5,18.16 92.08,18.16 92.08,24
GND on TOP: 154.05,0.25 154.05,68.33 0.25,68.33 0.25,0.25 ; 1 cut-out
GND on BOTTOM, L2_GND, L3_PWR, L5_GND, L6_PWR, L7_GND: 154.05,0.25 154.05,68.33 0.25,68.33 0.25,0.25
GND on L4_SIG: 154.05,0.25 154.05,68.33 0.25,68.33 0.25,0.25 ; 3 cut-outs
GND on L6_PWR: 40.64,67.94 40.64,52.7 76.2,52.7 76.2,67.94
GND on L6_PWR: 137.8,67.31 137.8,3.81 152.4,3.81 152.4,67.31
P3.3VCLK on BOTTOM: 119.63,9.53 119.63,12.19 121.28,12.19 121.54,12.45 121.54,16.89 125.86,16.89 126.24,16.51 127.25,16.51 127.25,13.97 124.33,13.97 123.83,13.46 123.83,10.16 121.54,10.16 121.54,9.53
P3.3VLMX on TOP: 108.97,18.67 108.97,15.75 116.84,15.75 116.84,18.67
P3.3VLMX on BOTTOM: 108.97,18.67 111.51,18.67 111.51,10.67 107.82,10.67 107.82,12.45 108.97,13.59
P4.5V on BOTTOM: 128.17,9.4 128.17,12.07 129.82,12.07 130.07,12.32 130.07,16.76 134.39,16.76 134.77,16.38 135.79,16.38 135.79,13.84 132.87,13.84 132.36,13.34 132.36,10.03 130.07,10.03 130.07,9.4
U17_BYPASS on BOTTOM: 75.49,15.39 75.49,17.81 77.27,19.58 87.81,19.58 87.81,17.42 78.54,17.42 77.9,16.79 77.9,15.39
N19879145 on TOP: 21.51,8.02 21.54,8.05 28.48,14.94 34.98,14.94 34.98,12.62 29.67,12.62 23.14,6.1 8.26,6.1 8.26,7.11 10.8,7.11 11.7,8.02
N19879167 on BOTTOM: 36.63,17.14 36.63,19.84 35.66,20.8 34.06,20.8 32.99,19.74 32.99,17.14
N19887756 on TOP: 92.96,64.87 92.96,66.83 97.49,66.83 97.49,66.62 98.81,65.28 98.81,61.52 98.7,61.42 97.71,61.42 97.61,61.52 97.61,64.49 97.28,64.82 93.01,64.82
N19887760 on TOP: 98.62,60.77 98.62,58.81 99.59,58.81 99.59,60.77
N19887762 on TOP: 98.58,52.1 98.58,54.05 99.64,54.05 99.64,52.1
N19887836 on TOP: 90.5,61.42 90.5,62.33 91.49,63.32 91.49,64.06 92.53,64.06 92.53,63.02 92.74,62.81 92.74,61.42
N19887836 on L6_PWR: 90.17,62.87 90.17,52.07 95.25,52.07 95.25,62.87
